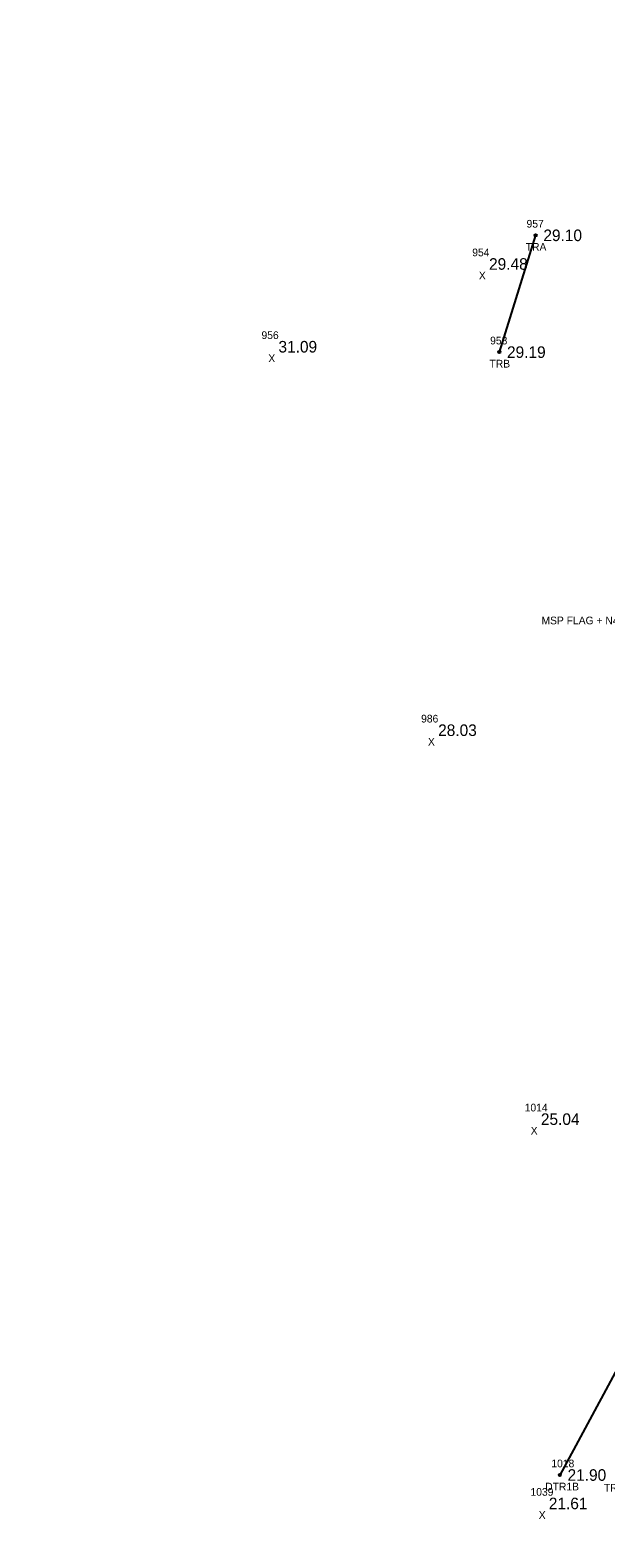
# Model space of a CAD drawing. Extents: x 2042117 to 2045853, y 303080 to 309569.
# Drawn here: x 2042788.5 to 2042863.2, y 306604.6 to 306800.2 of the extents above; entities that cross this region are included whole.
import ezdxf

# ---------------------------------------------------------------- set-up
doc = ezdxf.new("R2010")
doc.units = 0
for name, color, linetype in [('RD_EX_H2O', 7, 'Continuous'), ('RD_EX_H2O_txCode', 7, 'Continuous'), ('RD_EX_Misc_txCode', 7, 'Continuous'), ('RD_EX_TX_H2O_ELEV', 7, 'Continuous'), ('RD_EX_TX_Misc_ELEV', 7, 'Continuous'), ('RD_EX_TX_VEG_ELEV', 7, 'Continuous'), ('RD_EX_VEG', 7, 'Continuous'), ('RD_EX_VEG_txCode', 7, 'Continuous'), ('RD_HC_Cl', 7, 'Continuous'), ('RD_SMD_Locator', 7, 'Continuous')]:
    doc.layers.add(name, color=color, linetype=linetype)

msp = doc.modelspace()

# ---------------------------------------------------------------- linework, layer by layer
at = {"layer": 'RD_EX_H2O'}
msp.add_lwpolyline([(2042809.74, 307126.16), (2042806.56, 307122.63), (2042790.31, 307116.78), (2042788.49, 307114.78), (2042791.89, 307113.57), (2042804.81, 307114.94), (2042810.25, 307075.93), (2042820.25, 307025.92), (2042830.4, 306977.21), (2042843.29, 306928.12), (2042852.91, 306878.24), (2042864.55, 306828.43), (2042879.23, 306781.72), (2042889.45, 306748.73), (2042886.16, 306741.98), (2042888.34, 306727.94), (2042896.13, 306676.35), (2042885.67, 306665.43), (2042857.25, 306612.72)], dxfattribs=at)
at = {"layer": 'RD_EX_VEG'}
msp.add_line((2042854.11, 306773.62), (2042849.39, 306758.46), dxfattribs=at)
at = {"layer": 'RD_HC_Cl'}
msp.add_arc((2044751.25, 307348.43), 1911.29, 137.68184, 219.86836, dxfattribs=at)
at = {"layer": 'RD_SMD_Locator'}
for centre in [(2042854.11, 306773.62), (2042849.39, 306758.46), (2042857.25, 306612.72)]:
    msp.add_circle(centre, 0.15, dxfattribs=at)

# ---------------------------------------------------------------- texts
at = {"layer": 'RD_EX_H2O_txCode'}
for s, p in [('1018', (2042856.15, 306613.72)), ('DTR1B', (2042855.35, 306610.72))]:
    msp.add_text(s, height=1, dxfattribs=at).set_placement(p)
at = {"layer": 'RD_EX_Misc_txCode'}
for s, p in [('954', (2042845.88, 306770.9)), ('X', (2042846.74, 306767.9)), ('956', (2042818.52, 306760.16)), ('X', (2042819.41, 306757.16)), ('MSP FLAG + N410 E455 FS1', (2042854.87, 306723.13)), ('986', (2042839.24, 306710.39)), ('X', (2042840.13, 306707.39)), ('1014', (2042852.69, 306659.91)), ('X', (2042853.47, 306656.91)), ('1039', (2042853.44, 306610.03)), ('X', (2042854.51, 306607.03))]:
    msp.add_text(s, height=1, dxfattribs=at).set_placement(p)
at = {"layer": 'RD_EX_TX_H2O_ELEV'}
msp.add_text('21.90', height=1.5, dxfattribs=at).set_placement((2042858.25, 306611.97))
at = {"layer": 'RD_EX_TX_Misc_ELEV'}
for s, p in [('29.48', (2042848.06, 306769.15)), ('31.09', (2042820.72, 306758.41)), ('28.03', (2042841.45, 306708.64)), ('25.04', (2042854.79, 306658.16)), ('21.61', (2042855.82, 306608.28))]:
    msp.add_text(s, height=1.5, dxfattribs=at).set_placement(p)
at = {"layer": 'RD_EX_TX_VEG_ELEV'}
for s, p in [('29.10', (2042855.11, 306772.87)), ('29.19', (2042850.39, 306757.71))]:
    msp.add_text(s, height=1.5, dxfattribs=at).set_placement(p)
at = {"layer": 'RD_EX_VEG_txCode'}
for s, p in [('957', (2042852.93, 306774.62)), ('TRA', (2042852.83, 306771.62)), ('958', (2042848.2, 306759.46)), ('TRB', (2042848.12, 306756.46)), ('TRA', (2042862.97, 306610.56))]:
    msp.add_text(s, height=1, dxfattribs=at).set_placement(p)

doc.saveas('drawing.dxf')
